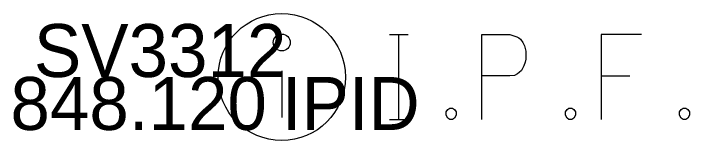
# Model space of a CAD drawing. Extents: x 2228183 to 2230895, y 679226 to 682223.
# Drawn here: x 2228183.49 to 2228196.23, y 680629.83 to 680632.23 of the extents above; entities that cross this region are included whole.
import ezdxf

# ---------------------------------------------------------------- set-up
doc = ezdxf.new("R2010")
doc.units = 0
for name, color, linetype in [('RS_Raster1', 7, 'Continuous'), ('SC_Scratch1', 7, 'Continuous'), ('SV_P_Control_Cells_Set', 7, 'Continuous'), ('SV_X_Text_Comment', 7, 'Continuous')]:
    doc.layers.add(name, color=color, linetype=linetype)

msp = doc.modelspace()

# ---------------------------------------------------------------- linework, layer by layer
at = {"layer": 'RS_Raster1'}
msp.add_line((2228188.543, 680631.149), (2228188.543, 680630.265), dxfattribs=at)
for points in [[(2228190.573, 680631.832), (2228190.926, 680631.832)], [(2228190.75, 680630.232), (2228190.75, 680631.832)], [(2228192.315, 680630.232), (2228192.315, 680631.832), (2228192.844, 680631.832), (2228192.899, 680631.819), (2228192.976, 680631.794), (2228193.01, 680631.769), (2228193.042, 680631.744), (2228193.087, 680631.681), (2228193.12, 680631.618), (2228193.142, 680631.517), (2228193.142, 680631.366), (2228193.131, 680631.315), (2228193.109, 680631.24), (2228193.065, 680631.152), (2228193.02, 680631.114), (2228192.987, 680631.089), (2228192.932, 680631.063), (2228192.844, 680631.051), (2228192.315, 680631.051)], [(2228195.324, 680631.832), (2228194.564, 680631.832), (2228194.564, 680630.232)], [(2228194.564, 680631.051), (2228195.104, 680631.051)], [(2228191.709, 680630.446), (2228191.764, 680630.446), (2228191.797, 680630.421), (2228191.83, 680630.371), (2228191.83, 680630.308), (2228191.797, 680630.257), (2228191.764, 680630.232), (2228191.709, 680630.232), (2228191.676, 680630.257), (2228191.643, 680630.308), (2228191.643, 680630.371), (2228191.676, 680630.421), (2228191.709, 680630.446)], [(2228193.957, 680630.446), (2228194.013, 680630.446), (2228194.046, 680630.421), (2228194.079, 680630.371), (2228194.079, 680630.308), (2228194.046, 680630.257), (2228194.013, 680630.232), (2228193.957, 680630.232), (2228193.924, 680630.257), (2228193.891, 680630.308), (2228193.891, 680630.371), (2228193.924, 680630.421), (2228193.957, 680630.446)], [(2228196.107, 680630.446), (2228196.162, 680630.446), (2228196.195, 680630.421), (2228196.228, 680630.371), (2228196.228, 680630.308), (2228196.195, 680630.257), (2228196.162, 680630.232), (2228196.107, 680630.232), (2228196.074, 680630.257), (2228196.041, 680630.308), (2228196.041, 680630.371), (2228196.074, 680630.421), (2228196.107, 680630.446)], [(2228190.573, 680630.232), (2228190.926, 680630.232)]]:
    msp.add_lwpolyline(points, dxfattribs=at)
for centre, radius in [((2228188.543, 680631.032), 1.2), ((2228188.543, 680631.684), 0.16)]:
    msp.add_circle(centre, radius, dxfattribs=at)

# ---------------------------------------------------------------- texts
at = {"layer": 'SC_Scratch1'}
msp.add_text('848.120', height=1, dxfattribs=at).set_placement((2228183.429, 680630.032))
at = {"layer": 'SV_P_Control_Cells_Set'}
msp.add_text('SV3312', height=1, dxfattribs=at).set_placement((2228183.872, 680631.032))
at = {"layer": 'SV_X_Text_Comment'}
msp.add_text('IPID', height=1, dxfattribs=at).set_placement((2228188.543, 680630.032))

doc.saveas('drawing.dxf')
